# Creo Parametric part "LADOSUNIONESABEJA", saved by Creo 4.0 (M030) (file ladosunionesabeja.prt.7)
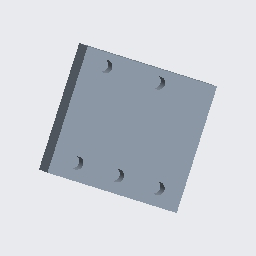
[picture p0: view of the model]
Units: millimeter Newton Second (mmNs); MM, TONNE, SECS

Created from: MMNS_PART_SOLID.PRT

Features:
  1. datum plane "RIGHT"
  2. datum plane "TOP"
  3. datum plane "FRONT"
  4. coordinate system
  5. sketch "Sketch 1"
  6. extrusion "Extrude 1"
  7. pattern "Pattern 1"
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
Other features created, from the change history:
  hole "Hole 1"
  hole "Hole 1 [2]"
  hole "Hole 1 [3]"
  hole "Hole 2"
  pattern "Patrón 2"
  hole "Taladro 2 [2]"
  hole "Hole 3"
  pattern "Pattern 3"
  hole "Hole 3 [2]"

Surfaces: 13 plane, 7 cylinder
